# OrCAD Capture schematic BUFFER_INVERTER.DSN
size A
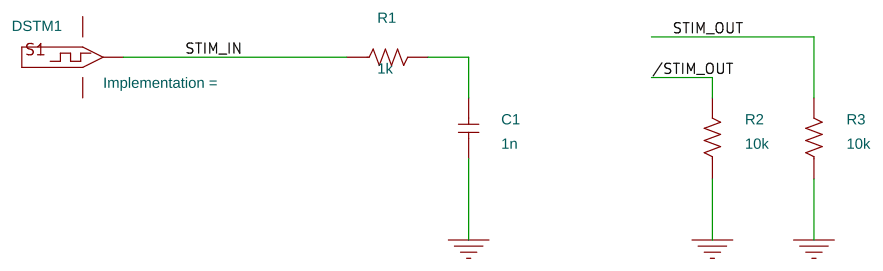
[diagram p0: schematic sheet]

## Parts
C1  1n  [cap196]
DSTM1  DigStim1
R1  1k  [AXRC05]
R2  10k  [AXRC05]
R3  10k  [AXRC05]

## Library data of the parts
C1 = C
DSTM1 = DigStim1
R1-R3 = R

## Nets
GND: DSTM1.3(GND)
VCC: DSTM1.2(VCC)
0: C1.1 R2.1 R3.1
/STIM_OUT: R2.2
STIM_IN: DSTM1.OUT R1.1
STIM_OUT: R3.2
N00116: C1.2 R1.2
